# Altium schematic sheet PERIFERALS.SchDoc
size A4; PageSetup: Record=PageOptions|CenterHorizontal=True|CenterVertical=True|PrintScale=0.70|XCorrection=1.00|YCorrection=1.00|PrintKind=0|BorderSize=5000000|LeftOffset=5|BottomOffset=0|Orientation=1|PaperLength=1000|PaperWidth=1000|Scale=100|PaperSource=7|PrintQuality=-4|MediaType=1|DitherType=10|PaperKind=A4|PrintScaleMode=1
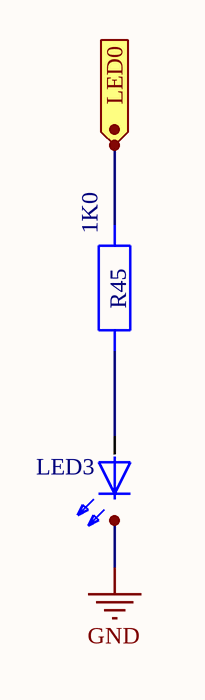
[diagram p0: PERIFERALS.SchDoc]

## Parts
LED3  LED_GN/1206  (value not drawn)
R45  value 1K0  (hidden comment: R12/1K0)

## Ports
LED0

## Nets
GND: LED3.K
LED0: R45.2 ; port LED0
NetLED3_A: LED3.A R45.1

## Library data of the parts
LED3 = LED_GN/1206: PART DESCE: LED GREEN max.30mA; TYPE: QTLP650C-4; VALUE: GREEN; GR: LA; PCB DECAL: O02X150Y0A0; SUPP.ART.#1: 359-9784; SUPP.#1: FARNELL; MFG.#1: FAIRCHILD
R45 = R12/1K0: PART DESCE: MINI-MELF 1% 1/4W or 1206; GR: R4; PCB DECAL: R02X125Y0A0; MFG.#1: BEYSCHLAG; SUPP.#1: BUERKLIN; SUPP.ART.#1: 06 E 664; Geometry.Height: 3.20040mm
